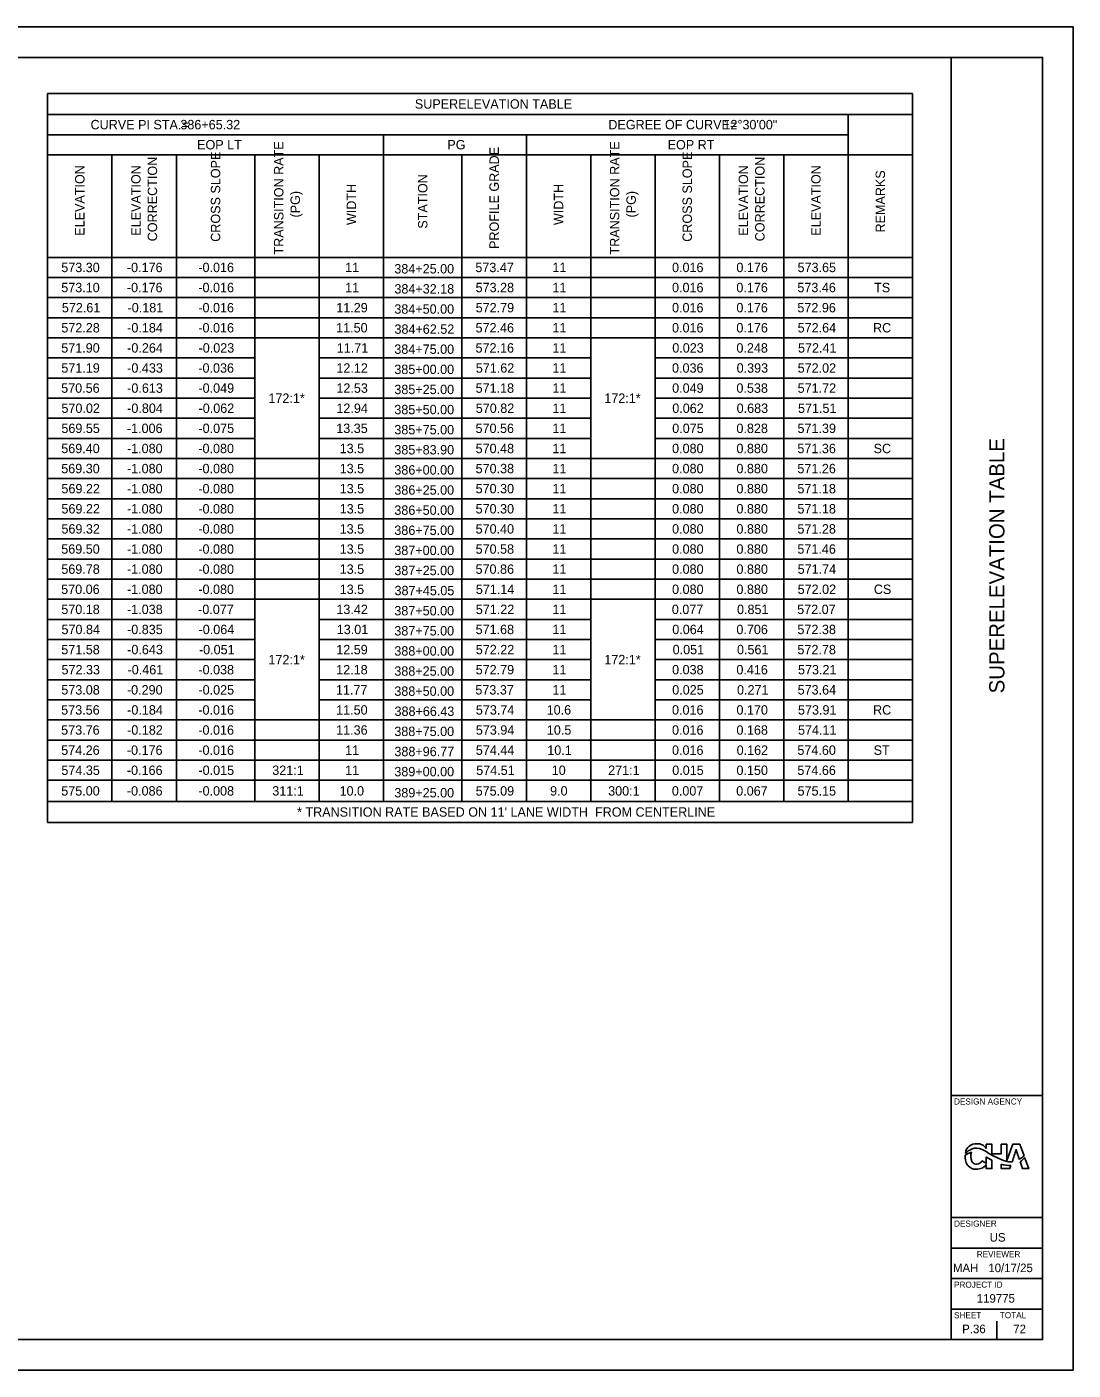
# Model space of a CAD drawing. Extents: x 0 to 34, y 0 to 22.
# Drawn here: x 16.86 to 34, y 0 to 22 of the extents above; entities that cross this region are included whole.
import ezdxf

# ---------------------------------------------------------------- set-up
doc = ezdxf.new("R2010")
doc.units = 0
for name, color, linetype in [('SH_Border', 7, 'Continuous'), ('SH_Cut_Line', 7, 'Continuous'), ('SH_Data', 7, 'Continuous'), ('SH_Text', 7, 'Continuous')]:
    doc.layers.add(name, color=color, linetype=linetype)

msp = doc.modelspace()

# ---------------------------------------------------------------- linework, layer by layer
at = {"layer": 'SH_Border'}
for p, q in [((32, 0.5), (32, 21.5)), ((32, 4.5), (33.5, 4.5)), ((32, 2.5), (33.5, 2.5)), ((32, 2), (33.5, 2)), ((32, 1.5), (33.5, 1.5)), ((32, 1), (33.5, 1))]:
    msp.add_line(p, q, dxfattribs=at)
msp.add_lwpolyline([(1.5, 21.5), (33.5, 21.5), (33.5, 0.5), (1.5, 0.5)], close=True, dxfattribs=at)
at = {"layer": 'SH_Cut_Line'}
msp.add_lwpolyline([(0, 0), (34, 0), (34, 22), (0, 22)], close=True, dxfattribs=at)
at = {"layer": 'SH_Data'}
for p, q in [((32.75, 3.5), (32.75, 3.5)), ((32.375, 0.675), (32.375, 0.675)), ((32.75, 0.5), (32.75, 0.8))]:
    msp.add_line(p, q, dxfattribs=at)
at = {"layer": 'SH_Text'}
for p, q in [((17.205, 20.91), (31.37, 20.91)), ((17.205, 20.91), (17.205, 8.968)), ((31.37, 20.91), (31.37, 8.968)), ((17.205, 20.564), (31.37, 20.564)), ((30.315, 20.564), (30.315, 9.314)), ((17.205, 20.234), (30.315, 20.234)), ((22.706, 20.234), (22.706, 9.314)), ((25.045, 20.234), (25.045, 9.314)), ((17.205, 19.905), (31.37, 19.905)), ((18.259, 19.905), (18.259, 9.314)), ((19.313, 19.905), (19.313, 9.314)), ((20.598, 19.905), (20.598, 9.314)), ((21.652, 19.905), (21.652, 9.314)), ((23.991, 19.905), (23.991, 9.314)), ((26.099, 19.905), (26.099, 9.314)), ((27.153, 19.905), (27.153, 9.314)), ((28.207, 19.905), (28.207, 9.314)), ((29.261, 19.905), (29.261, 9.314)), ((17.205, 18.225), (31.37, 18.225)), ((17.205, 17.895), (31.37, 17.895)), ((17.205, 17.566), (31.37, 17.566)), ((17.205, 17.237), (31.37, 17.237)), ((17.205, 16.907), (31.37, 16.907)), ((17.205, 16.578), (20.598, 16.578)), ((21.652, 16.578), (26.099, 16.578)), ((27.153, 16.578), (31.37, 16.578)), ((17.205, 16.248), (20.598, 16.248)), ((21.652, 16.248), (26.099, 16.248)), ((27.153, 16.248), (31.37, 16.248)), ((17.205, 15.919), (20.598, 15.919)), ((21.652, 15.919), (26.099, 15.919)), ((27.153, 15.919), (31.37, 15.919)), ((17.205, 15.59), (20.598, 15.59)), ((21.652, 15.59), (26.099, 15.59)), ((27.153, 15.59), (31.37, 15.59)), ((17.205, 15.26), (20.598, 15.26)), ((21.652, 15.26), (26.099, 15.26)), ((27.153, 15.26), (31.37, 15.26)), ((17.205, 14.931), (31.37, 14.931)), ((17.205, 14.601), (31.37, 14.601)), ((17.205, 14.272), (31.37, 14.272)), ((17.205, 13.942), (31.37, 13.942)), ((17.205, 13.613), (31.37, 13.613)), ((17.205, 13.284), (31.37, 13.284)), ((17.205, 12.954), (31.37, 12.954)), ((17.205, 12.625), (31.37, 12.625)), ((17.205, 12.295), (20.598, 12.295)), ((21.652, 12.295), (26.099, 12.295)), ((27.153, 12.295), (31.37, 12.295)), ((17.205, 11.966), (20.598, 11.966)), ((21.652, 11.966), (26.099, 11.966)), ((27.153, 11.966), (31.37, 11.966)), ((17.205, 11.637), (20.598, 11.637)), ((21.652, 11.637), (26.099, 11.637)), ((27.153, 11.637), (31.37, 11.637)), ((17.205, 11.307), (20.598, 11.307)), ((21.652, 11.307), (26.099, 11.307)), ((27.153, 11.307), (31.37, 11.307)), ((17.205, 10.978), (20.598, 10.978)), ((21.652, 10.978), (26.099, 10.978)), ((27.153, 10.978), (31.37, 10.978)), ((17.205, 10.648), (31.37, 10.648)), ((17.205, 10.319), (31.37, 10.319)), ((17.205, 9.989), (31.37, 9.989)), ((17.205, 9.66), (31.37, 9.66)), ((17.205, 9.314), (31.37, 9.314)), ((17.205, 8.968), (31.37, 8.968)), ((33.066, 3.619), (33.069, 3.619))]:
    msp.add_line(p, q, dxfattribs=at)
for points in [[(33.196, 3.508), (33.126, 3.7), (33.012, 3.7), (32.915, 3.431), (32.915, 3.7), (32.822, 3.7), (32.822, 3.543), (32.669, 3.543), (32.669, 3.7), (32.576, 3.7), (32.576, 3.629)], [(32.576, 3.492), (32.576, 3.389), (32.507, 3.43)], [(32.576, 3.37), (32.576, 3.3), (32.669, 3.3), (32.669, 3.439)], [(32.822, 3.373), (32.822, 3.3), (32.867, 3.3), (32.915, 3.3), (32.964, 3.3), (32.981, 3.351)], [(33.133, 3.413), (33.144, 3.383), (33.173, 3.3), (33.272, 3.3), (33.206, 3.481)]]:
    msp.add_lwpolyline(points, dxfattribs=at)
for centre, radius, start, end in [((32.471, 3.495), 0.242, 173.6843, 214.2778), ((32.441, 3.209), 0.376, 105.7483, 123.9538), ((32.414, 3.529), 0.181, 129.6629, 172.5664), ((32.505, 3.249), 0.407, 114.8364, 131.7457), ((32.418, 3.503), 0.205, 88.0817, 126.0325), ((32.516, 3.499), 0.192, 157.8882, 204.8663), ((32.417, 3.436), 0.201, 63.1724, 114.4396), ((32.43, 3.514), 0.194, 64.9016, 91.2438), ((32.183, 2.916), 0.771, 57.2913, 65.1), ((32.442, 3.551), 0.155, 30.3756, 63.3712), ((33.592, 5.1), 1.829, 237.1308, 240.4227), ((31.298, 4.056), 1.821, 339.3263, 346.125), ((34.073, 3.831), 1.026, 191.9132, 201.6837), ((32.347, 3.41), 0.0923, 214.2778, 222.6269), ((32.407, 3.465), 0.174, 222.6269, 271.9347), ((32.404, 3.447), 0.0681, 204.8663, 223.055), ((32.418, 3.46), 0.0871, 223.055, 273.5972), ((32.423, 3.511), 0.219, 267.5421, 292.3552), ((32.424, 3.461), 0.0879, 269.2163, 339.4439), ((32.441, 3.453), 0.159, 294.1165, 328.289), ((33.232, 4.512), 1.213, 237.2686, 242.3197), ((33.204, 4.445), 1.067, 241.1998, 252.5446), ((32.953, 3.737), 0.386, 250.2087, 274.1935), ((32.979, 3.72), 0.308, 251.9229, 274.261), ((32.877, 3.865), 0.479, 300.42, 311.7894), ((32.822, 3.823), 0.515, 307.219, 318.2934)]:
    msp.add_arc(centre, radius, start, end, dxfattribs=at)

# ---------------------------------------------------------------- texts
at = {"layer": 'SH_Data'}
msp.add_text('SUPERELEVATION TABLE', height=0.25, rotation=90, dxfattribs=at).set_placement((32.875, 11.084))
for s, height, p in [('DESIGN AGENCY', 0.1, (32.05, 4.35)), ('DESIGNER', 0.1, (32.05, 2.35)), ('US', 0.14, (32.633, 2.105)), ('REVIEWER', 0.1, (32.422, 1.85)), ('MAH', 0.14, (32.032, 1.605)), ('10/17/25', 0.14, (32.611, 1.605)), ('PROJECT ID', 0.1, (32.05, 1.35)), ('119775', 0.14, (32.421, 1.105)), ('SHEET', 0.1, (32.05, 0.85)), ('TOTAL', 0.1, (32.8, 0.85)), ('P.36', 0.14, (32.183, 0.605)), ('72', 0.14, (33.019, 0.605))]:
    msp.add_text(s, height=height, dxfattribs=at).set_placement(p)
at = {"layer": 'SH_Text'}
for s, p in [('SUPERELEVATION TABLE', (23.219, 20.66)), ('CURVE PI STA.=', (17.908, 20.322)), ('386+65.32', (19.379, 20.322)), ('DEGREE OF CURVE=', (26.388, 20.322)), ('12°30\'00"', (28.273, 20.322)), ('EOP LT', (19.653, 19.993)), ('PG', (23.751, 19.993)), ('EOP RT', (27.359, 19.993)), ('573.30', (17.428, 17.983)), ('-0.176', (18.503, 17.983)), ('-0.016', (19.673, 17.983)), ('11', (22.078, 17.983)), ('384+25.00', (22.883, 17.961)), ('573.47', (24.21, 17.983)), ('11', (25.471, 17.983)), ('0.016', (27.431, 17.983)), ('0.176', (28.485, 17.983)), ('573.65', (29.487, 17.983)), ('573.10', (17.428, 17.654)), ('-0.176', (18.503, 17.654)), ('-0.016', (19.673, 17.654)), ('11', (22.078, 17.654)), ('384+32.18', (22.884, 17.632)), ('573.28', (24.214, 17.654)), ('11', (25.471, 17.654)), ('0.016', (27.431, 17.654)), ('0.176', (28.485, 17.654)), ('573.46', (29.484, 17.654)), ('TS', (30.74, 17.654)), ('572.61', (17.438, 17.324)), ('-0.181', (18.514, 17.324)), ('-0.016', (19.673, 17.324)), ('11.29', (21.932, 17.324)), ('384+50.00', (22.883, 17.302)), ('572.79', (24.215, 17.324)), ('11', (25.471, 17.324)), ('0.016', (27.431, 17.324)), ('0.176', (28.485, 17.324)), ('572.96', (29.484, 17.324)), ('572.28', (17.429, 16.995)), ('-0.184', (18.508, 16.995)), ('-0.016', (19.673, 16.995)), ('11.50', (21.93, 16.995)), ('384+62.52', (22.885, 16.973)), ('572.46', (24.213, 16.995)), ('11', (25.471, 16.995)), ('0.016', (27.431, 16.995)), ('0.176', (28.485, 16.995)), ('572.64', (29.488, 16.995)), ('RC', (30.723, 16.995)), ('571.90', (17.428, 16.665)), ('-0.264', (18.508, 16.665)), ('-0.023', (19.677, 16.665)), ('11.71', (21.94, 16.665)), ('384+75.00', (22.883, 16.644)), ('572.16', (24.213, 16.665)), ('11', (25.471, 16.665)), ('0.023', (27.435, 16.665)), ('0.248', (28.486, 16.665)), ('572.41', (29.494, 16.665)), ('571.19', (17.429, 16.336)), ('-0.433', (18.508, 16.336)), ('-0.036', (19.673, 16.336)), ('12.12', (21.934, 16.336)), ('385+00.00', (22.883, 16.314)), ('571.62', (24.217, 16.336)), ('11', (25.471, 16.336)), ('0.036', (27.431, 16.336)), ('0.393', (28.489, 16.336)), ('572.02', (29.488, 16.336)), ('570.56', (17.427, 16.007)), ('-0.613', (18.508, 16.007)), ('-0.049', (19.675, 16.007)), ('12.53', (21.934, 16.007)), ('385+25.00', (22.883, 15.985)), ('571.18', (24.214, 16.007)), ('11', (25.471, 16.007)), ('0.049', (27.433, 16.007)), ('0.538', (28.486, 16.007)), ('571.72', (29.488, 16.007)), ('172:1*', (20.821, 15.842)), ('172:1*', (26.322, 15.842)), ('570.02', (17.431, 15.677)), ('-0.804', (18.508, 15.677)), ('-0.062', (19.677, 15.677)), ('12.94', (21.934, 15.677)), ('385+50.00', (22.883, 15.655)), ('570.82', (24.217, 15.677)), ('11', (25.471, 15.677)), ('0.062', (27.435, 15.677)), ('0.683', (28.489, 15.677)), ('571.51', (29.494, 15.677)), ('569.55', (17.43, 15.348)), ('-1.006', (18.503, 15.348)), ('-0.075', (19.675, 15.348)), ('13.35', (21.932, 15.348)), ('385+75.00', (22.883, 15.326)), ('570.56', (24.213, 15.348)), ('11', (25.471, 15.348)), ('0.075', (27.434, 15.348)), ('0.828', (28.486, 15.348)), ('571.39', (29.486, 15.348)), ('569.40', (17.428, 15.018)), ('-1.080', (18.504, 15.018)), ('-0.080', (19.673, 15.018)), ('13.5', (21.988, 15.018)), ('385+83.90', (22.883, 14.997)), ('570.48', (24.214, 15.018)), ('11', (25.471, 15.018)), ('0.080', (27.432, 15.018)), ('0.880', (28.486, 15.018)), ('571.36', (29.484, 15.018)), ('SC', (30.732, 15.018)), ('569.30', (17.428, 14.689)), ('-1.080', (18.504, 14.689)), ('-0.080', (19.673, 14.689)), ('13.5', (21.988, 14.689)), ('386+00.00', (22.883, 14.667)), ('570.38', (24.214, 14.689)), ('11', (25.471, 14.689)), ('0.080', (27.432, 14.689)), ('0.880', (28.486, 14.689)), ('571.26', (29.484, 14.689)), ('569.22', (17.431, 14.36)), ('-1.080', (18.504, 14.36)), ('-0.080', (19.673, 14.36)), ('13.5', (21.988, 14.36)), ('386+25.00', (22.883, 14.338)), ('570.30', (24.214, 14.36)), ('11', (25.471, 14.36)), ('0.080', (27.432, 14.36)), ('0.880', (28.486, 14.36)), ('571.18', (29.485, 14.36)), ('569.22', (17.431, 14.03)), ('-1.080', (18.504, 14.03)), ('-0.080', (19.673, 14.03)), ('13.5', (21.988, 14.03)), ('386+50.00', (22.883, 14.008)), ('570.30', (24.214, 14.03)), ('11', (25.471, 14.03)), ('0.080', (27.432, 14.03)), ('0.880', (28.486, 14.03)), ('571.18', (29.485, 14.03)), ('569.32', (17.431, 13.701)), ('-1.080', (18.504, 13.701)), ('-0.080', (19.673, 13.701)), ('13.5', (21.988, 13.701)), ('386+75.00', (22.883, 13.679)), ('570.40', (24.214, 13.701)), ('11', (25.471, 13.701)), ('0.080', (27.432, 13.701)), ('0.880', (28.486, 13.701)), ('571.28', (29.485, 13.701)), ('569.50', (17.428, 13.371)), ('-1.080', (18.504, 13.371)), ('-0.080', (19.673, 13.371)), ('13.5', (21.988, 13.371)), ('387+00.00', (22.883, 13.349)), ('570.58', (24.214, 13.371)), ('11', (25.471, 13.371)), ('0.080', (27.432, 13.371)), ('0.880', (28.486, 13.371)), ('571.46', (29.484, 13.371)), ('569.78', (17.429, 13.042)), ('-1.080', (18.504, 13.042)), ('-0.080', (19.673, 13.042)), ('13.5', (21.988, 13.042)), ('387+25.00', (22.883, 13.02)), ('570.86', (24.213, 13.042)), ('11', (25.471, 13.042)), ('0.080', (27.432, 13.042)), ('0.880', (28.486, 13.042)), ('571.74', (29.488, 13.042)), ('570.06', (17.427, 12.712)), ('-1.080', (18.504, 12.712)), ('-0.080', (19.673, 12.712)), ('13.5', (21.988, 12.712)), ('387+45.05', (22.886, 12.691)), ('571.14', (24.218, 12.712)), ('11', (25.471, 12.712)), ('0.080', (27.432, 12.712)), ('0.880', (28.486, 12.712)), ('572.02', (29.488, 12.712)), ('CS', (30.736, 12.712)), ('570.18', (17.429, 12.383)), ('-1.038', (18.505, 12.383)), ('-0.077', (19.67, 12.383)), ('13.42', (21.934, 12.383)), ('387+50.00', (22.883, 12.361)), ('571.22', (24.217, 12.383)), ('11', (25.471, 12.383)), ('0.077', (27.428, 12.383)), ('0.851', (28.495, 12.383)), ('572.07', (29.481, 12.383)), ('570.84', (17.432, 12.054)), ('-0.835', (18.506, 12.054)), ('-0.064', (19.677, 12.054)), ('13.01', (21.94, 12.054)), ('387+75.00', (22.883, 12.032)), ('571.68', (24.214, 12.054)), ('11', (25.471, 12.054)), ('0.064', (27.435, 12.054)), ('0.706', (28.485, 12.054)), ('572.38', (29.485, 12.054)), ('571.58', (17.429, 11.724)), ('-0.643', (18.508, 11.724)), ('-0.051', (19.683, 11.724)), ('12.59', (21.932, 11.724)), ('572.22', (24.217, 11.724)), ('0.051', (27.441, 11.724)), ('0.561', (28.495, 11.724)), ('572.78', (29.485, 11.724)), ('172:1*', (20.821, 11.56)), ('388+00.00', (22.883, 11.702)), ('11', (25.471, 11.724)), ('172:1*', (26.322, 11.56)), ('572.33', (17.432, 11.395)), ('-0.461', (18.514, 11.395)), ('-0.038', (19.674, 11.395)), ('12.18', (21.931, 11.395)), ('388+25.00', (22.883, 11.373)), ('572.79', (24.215, 11.395)), ('11', (25.471, 11.395)), ('0.038', (27.432, 11.395)), ('0.416', (28.485, 11.395)), ('573.21', (29.494, 11.395)), ('573.08', (17.429, 11.065)), ('-0.290', (18.504, 11.065)), ('-0.025', (19.675, 11.065)), ('573.37', (24.21, 11.065)), ('0.025', (27.434, 11.065)), ('0.271', (28.495, 11.065)), ('573.64', (29.488, 11.065)), ('11.77', (21.927, 11.065)), ('388+50.00', (22.883, 11.044)), ('11', (25.471, 11.065)), ('573.56', (17.427, 10.736)), ('-0.184', (18.508, 10.736)), ('-0.016', (19.673, 10.736)), ('11.50', (21.93, 10.736)), ('388+66.43', (22.886, 10.714)), ('573.74', (24.218, 10.736)), ('10.6', (25.378, 10.736)), ('0.016', (27.431, 10.736)), ('0.170', (28.486, 10.736)), ('573.91', (29.494, 10.736)), ('RC', (30.723, 10.736)), ('573.76', (17.427, 10.407)), ('-0.182', (18.507, 10.407)), ('-0.016', (19.673, 10.407)), ('11.36', (21.93, 10.407)), ('573.94', (24.218, 10.407)), ('10.5', (25.381, 10.407)), ('0.016', (27.431, 10.407)), ('0.168', (28.486, 10.407)), ('574.11', (29.494, 10.407)), ('388+75.00', (22.883, 10.385)), ('574.26', (17.427, 10.077)), ('-0.176', (18.503, 10.077)), ('-0.016', (19.673, 10.077)), ('11', (22.078, 10.077)), ('388+96.77', (22.884, 10.055)), ('574.44', (24.218, 10.077)), ('10.1', (25.388, 10.077)), ('0.016', (27.431, 10.077)), ('0.162', (28.489, 10.077)), ('574.60', (29.484, 10.077)), ('ST', (30.733, 10.077)), ('574.35', (17.43, 9.748)), ('-0.166', (18.503, 9.748)), ('-0.015', (19.675, 9.748)), ('321:1', (20.884, 9.748)), ('11', (22.078, 9.748)), ('574.51', (24.224, 9.748)), ('10', (25.461, 9.748)), ('271:1', (26.385, 9.748)), ('0.015', (27.434, 9.748)), ('0.150', (28.486, 9.748)), ('574.66', (29.484, 9.748)), ('389+00.00', (22.883, 9.726)), ('575.00', (17.428, 9.41)), ('-0.086', (18.503, 9.41)), ('-0.008', (19.674, 9.41)), ('311:1', (20.884, 9.41)), ('10.0', (21.986, 9.41)), ('389+25.00', (22.883, 9.38)), ('575.09', (24.215, 9.41)), ('9.0', (25.434, 9.41)), ('300:1', (26.385, 9.41)), ('0.007', (27.428, 9.41)), ('0.067', (28.482, 9.41)), ('575.15', (29.487, 9.41)), ("* TRANSITION RATE BASED ON 11' LANE WIDTH  FROM CENTERLINE", (21.29, 9.064))]:
    msp.add_text(s, height=0.154, dxfattribs=at).set_placement(p)
for s, p in [('TRANSITION RATE ', (21.067, 18.272)), ('PROFILE GRADE', (24.595, 18.363)), ('TRANSITION RATE ', (26.568, 18.272)), ('CORRECTION', (18.998, 18.488)), ('CROSS SLOPE', (20.032, 18.48)), ('CROSS SLOPE', (27.757, 18.48)), ('CORRECTION', (28.946, 18.488)), ('ELEVATION', (17.809, 18.579)), ('ELEVATION ', (18.728, 18.579)), ('ELEVATION ', (28.676, 18.579)), ('ELEVATION', (29.865, 18.579)), ('REMARKS', (30.919, 18.632)), ('WIDTH', (22.256, 18.754)), ('STATION', (23.425, 18.695)), ('WIDTH', (25.649, 18.754)), ('(PG)', (21.337, 18.878)), ('(PG)', (26.838, 18.878))]:
    msp.add_text(s, height=0.154, rotation=90, dxfattribs=at).set_placement(p)

doc.saveas('drawing.dxf')
